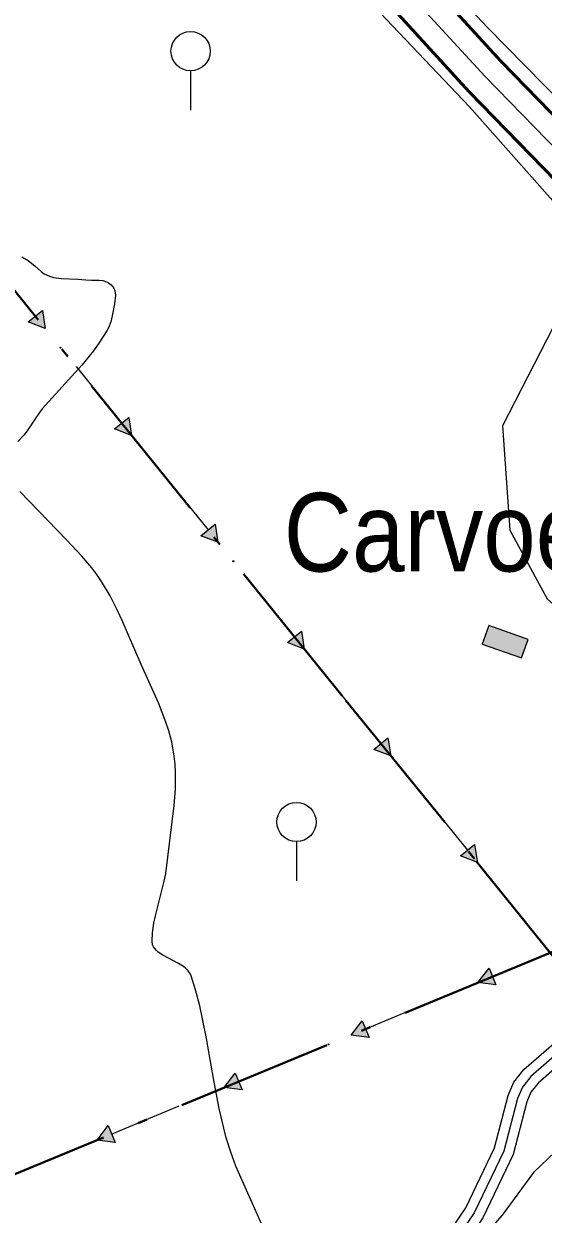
# Model space of a CAD drawing. Extents: x -64005 to -55000, y -89025 to -80000.
# Drawn here: x -59043 to -58513, y -83877 to -82664 of the extents above; entities that cross this region are included whole.
import ezdxf
from ezdxf.enums import TextEntityAlignment as Align

# ---------------------------------------------------------------- set-up
doc = ezdxf.new("R2010")
doc.units = 0
doc.header["$LTSCALE"] = 32
doc.linetypes.add('DOT_DASHED', pattern=[7.7, 5, -1.2, 0.3, -1.2])
doc.linetypes.add('LONG_DASHED', pattern=[7.5, 6, -1.5])
for name, color, linetype, lineweight in [('18', 7, 'Continuous', 25), ('2', 7, 'Continuous', 25), ('24', 7, 'Continuous', 25), ('32', 7, 'Continuous', 25), ('39', 7, 'LONG_DASHED', 25), ('7', 7, 'Continuous', 13), ('8', 7, 'Continuous', 25)]:
    doc.layers.add(name, color=color, linetype=linetype, lineweight=lineweight)
doc.layers.add('45', color=7, linetype='Continuous')

msp = doc.modelspace()

# ---------------------------------------------------------------- hatches: boundary and pattern name
at = {"layer": '18'}
for points in [[(-59023.97, -82956.59), (-59021.09, -82974.86), (-59038.36, -82968.22)], [(-58935.95, -83065.45), (-58933.07, -83083.72), (-58950.33, -83077.08)], [(-58847.92, -83174.32), (-58845.04, -83192.59), (-58862.3, -83185.95)], [(-58759.89, -83283.18), (-58757.01, -83301.45), (-58774.28, -83294.81)], [(-58671.78, -83391.94), (-58668.86, -83410.21), (-58686.14, -83403.61)], [(-58583.5, -83500.6), (-58580.58, -83518.87), (-58597.86, -83512.27)], [(-58561.62, -83643.68), (-58579.96, -83641.25), (-58568.69, -83626.58)], [(-58691.01, -83697.15), (-58709.35, -83694.72), (-58698.07, -83680.06)], [(-58820.39, -83750.63), (-58838.73, -83748.2), (-58827.46, -83733.53)], [(-58949.78, -83804.11), (-58968.11, -83801.68), (-58956.84, -83787.01)]]:
    msp.add_hatch(color=256, dxfattribs=at).paths.add_polyline_path(points)
at = {"layer": '7'}
msp.add_hatch(color=256, dxfattribs=at).paths.add_polyline_path([(-58528.85, -83291.63), (-58568.93, -83277.49), (-58575.59, -83296.35), (-58535.51, -83310.49)])

# ---------------------------------------------------------------- linework, layer by layer
at = {"layer": '18'}
for p, q in [((-59077.68, -82904.88), (-59031.16, -82962.4)), ((-58989.65, -83013.74), (-58943.14, -83071.27)), ((-58901.63, -83122.6), (-58855.11, -83180.13)), ((-58813.6, -83231.47), (-58767.09, -83289)), ((-58637.33, -83449.02), (-58590.68, -83506.44)), ((-58626.17, -83660.35), (-58694.54, -83688.61)), ((-58755.55, -83713.82), (-58823.92, -83742.08)), ((-58884.94, -83767.3), (-58953.31, -83795.56)), ((-59014.32, -83820.78), (-59082.69, -83849.03))]:
    msp.add_line(p, q, dxfattribs=at)
at = {"layer": '18', "linetype": 'DOT_DASHED', "lineweight": 40}
for points in [[(-55000.81, -81341.27), (-57492.65, -83191.85), (-58506.34, -83610.82), (-59176.97, -83888), (-59245.7, -83916.4), (-60498.5, -84434.2), (-61697.45, -84700.56), (-63379.7, -85074.29), (-63500.32, -85101.08), (-63736.4, -85153.53), (-64000, -85168.65)], [(-60219.71, -81521.05), (-59978.44, -81794.82), (-59646.58, -82111.37), (-59468.07, -82280.13), (-59415, -82487.84), (-59283.25, -82645.5), (-59128.86, -82841.58), (-58714.75, -83353.72), (-58581.73, -83517.45), (-58506.34, -83610.82), (-58347.94, -83807.01), (-58247.59, -83933.66), (-58191.9, -84001.28), (-58164.58, -84034.46), (-58137.14, -84068.11), (-57960.33, -84286.53), (-57797.76, -84487.35), (-57624.25, -84702.51), (-57366.28, -84880.22), (-57249.59, -84960.27), (-57114.47, -85053.89), (-56518.68, -85641.19), (-56404.54, -85755.57)]]:
    msp.add_lwpolyline(points, dxfattribs=at)
at = {"layer": '18'}
for points in [[(-59023.97, -82956.59), (-59021.09, -82974.86), (-59038.36, -82968.22)], [(-58935.95, -83065.45), (-58933.07, -83083.72), (-58950.33, -83077.08)], [(-58847.92, -83174.32), (-58845.04, -83192.59), (-58862.3, -83185.95)], [(-58759.89, -83283.18), (-58757.01, -83301.45), (-58774.28, -83294.81)], [(-58671.78, -83391.94), (-58668.86, -83410.21), (-58686.14, -83403.61)], [(-58583.5, -83500.6), (-58580.58, -83518.87), (-58597.86, -83512.27)], [(-58561.62, -83643.68), (-58579.96, -83641.25), (-58568.69, -83626.58)], [(-58691.01, -83697.15), (-58709.35, -83694.72), (-58698.07, -83680.06)], [(-58820.39, -83750.63), (-58838.73, -83748.2), (-58827.46, -83733.53)], [(-58949.78, -83804.11), (-58968.11, -83801.68), (-58956.84, -83787.01)]]:
    msp.add_lwpolyline(points, close=True, dxfattribs=at)
for points in [[(-58725.58, -83340.33), (-58714.75, -83353.72), (-58678.96, -83397.78)], [(-58549.17, -83557.77), (-58506.34, -83610.82), (-58502.7, -83615.33)], [(-58496.79, -83606.87), (-58506.34, -83610.82), (-58565.16, -83635.13)]]:
    msp.add_lwpolyline(points, dxfattribs=at)
for centre in [(-59005.37, -82994.3), (-58917.35, -83103.16), (-58829.32, -83212.03), (-58741.29, -83320.89), (-58653.09, -83429.61), (-58564.88, -83538.32), (-58603.06, -83650.8), (-58732.45, -83704.27), (-58861.83, -83757.75), (-58991.22, -83811.23)]:
    msp.add_circle(centre, 0.5, dxfattribs=at)
at = {"layer": '2', "lineweight": 53}
for points in [[(-58005.27, -83210), (-58013.89, -83203.14), (-58085.56, -83146.74), (-58171.15, -83072.46), (-58241.42, -83010.49), (-58351.28, -82909.11), (-58468.76, -82792.74), (-58556.36, -82702.67), (-58631.88, -82620.43), (-58703.26, -82540.92), (-58753.22, -82482.19), (-58802.18, -82423.2), (-58818.32, -82403.45)], [(-58033.51, -83245.03), (-58041.81, -83238.44), (-58114.24, -83181.44), (-58200.79, -83106.32), (-58271.56, -83043.91), (-58382.38, -82941.65), (-58500.72, -82824.42), (-58589.06, -82733.59), (-58665.2, -82650.69), (-58737.14, -82570.54), (-58787.68, -82511.13), (-58836.92, -82451.8), (-58853.29, -82431.77)]]:
    msp.add_lwpolyline(points, dxfattribs=at)
at = {"layer": '2'}
msp.add_lwpolyline([(-58019.39, -83227.52), (-58027.85, -83220.79), (-58099.9, -83164.09), (-58185.97, -83089.39), (-58256.49, -83027.2), (-58366.83, -82925.38), (-58484.74, -82808.58), (-58572.71, -82718.13), (-58648.54, -82635.56), (-58720.2, -82555.73), (-58770.45, -82496.66), (-58819.55, -82437.5), (-58835.8, -82417.61)], dxfattribs=at)
at = {"layer": '24'}
for points in [[(-59131.54, -82081.79), (-59021.28, -82238.07), (-58929.28, -82357.85), (-58846.39, -82457.48), (-58725.49, -82604.65), (-58588.62, -82749.15), (-58445.66, -82910.38), (-58503.43, -82973.52), (-58555.12, -83073.93), (-58547.5, -83180.41), (-58509.48, -83250.39), (-58386.3, -83360.66), (-58306.46, -83419.22), (-58225.88, -83296.75), (-58159.75, -83181.12), (-58131.62, -83203.18), (-58038.09, -83303.57), (-57977.77, -83366.49)], [(-57562.93, -83483.87), (-57612.28, -83458.71), (-57795.53, -83316.12), (-57916.42, -83244.63), (-58069.26, -83129.04), (-58158.22, -83044.62), (-58191.68, -83037.78), (-58357.46, -82884.53), (-58570.37, -82668.16), (-58698.88, -82531.26), (-58808.38, -82396.65), (-58888.98, -82290.17), (-58953.16, -82217.01)], [(-58800.72, -83887.2), (-58826.72, -83828.35), (-58831.99, -83813.99), (-58836.5, -83799.34), (-58839.15, -83789.44), (-58843.78, -83769.37), (-58849.55, -83738.87), (-58856.65, -83698.14), (-58860.61, -83678.04), (-58863.6, -83664.83), (-58867.89, -83648.59), (-58872.4, -83634.3), (-58873.14, -83632.54), (-58875.25, -83629.36), (-58878.06, -83626.53), (-58880.26, -83624.82), (-58885.21, -83621.71), (-58901.3, -83613.28), (-58905.86, -83610.2), (-58907.8, -83608.52), (-58910.73, -83604.75), (-58911.64, -83602.62), (-58912.19, -83599.06), (-58911.77, -83590.44), (-58910.4, -83580.81), (-58908.8, -83573.08), (-58899.75, -83537.99), (-58898.13, -83530.13), (-58889.48, -83460.97), (-58888.25, -83444.03), (-58888.11, -83427.17), (-58888.58, -83418.78), (-58889.48, -83410.42), (-58892.15, -83395.96), (-58895.14, -83384.7), (-58898, -83375.8), (-58905.61, -83356.08), (-58923.26, -83317.12), (-58942.59, -83272.48), (-58947.33, -83262.17), (-58954.99, -83247.06), (-58963.62, -83232.55), (-58968.42, -83225.58), (-58973.58, -83218.83), (-58983.89, -83206.87), (-58999.37, -83190), (-59047.05, -83140.92)], [(-58423.67, -83812.69), (-58447.31, -83806.67), (-58470.12, -83805.91), (-58501.29, -83813.52), (-58523.34, -83834.83), (-58555.27, -83878.19), (-58582.63, -83909), (-58629.77, -83962.25), (-58674.78, -84023.88)]]:
    msp.add_lwpolyline(points, dxfattribs=at)
at = {"layer": '32'}
for p, q in [((-58872.87, -82712.35), (-58872.87, -82752.35)), ((-58764.98, -83497.66), (-58764.98, -83537.66))]:
    msp.add_line(p, q, dxfattribs=at)
for centre in [(-58872.87, -82692.35), (-58764.98, -83477.66)]:
    msp.add_circle(centre, 20, dxfattribs=at)
at = {"layer": '39'}
msp.add_lwpolyline([(-58360.97, -83600.52), (-58414.02, -83637.24), (-58428.6, -83648.81), (-58480.78, -83697.38), (-58526.08, -83736.8), (-58534.63, -83747.86), (-58539.65, -83759.43), (-58553.66, -83813.01), (-58583.81, -83875.86), (-58627.03, -83939.3), (-58636.07, -83954.8), (-58676.14, -84024.52), (-58682.72, -84046.47), (-58685.23, -84066.58), (-58686.74, -84087.2), (-58681.21, -84129.43), (-58665.83, -84178.22), (-58657.1, -84191.64), (-58643.54, -84203.21), (-58624.04, -84214.06), (-58543.46, -84255.87)], dxfattribs=at)
at = {"layer": '7', "lineweight": 25}
msp.add_lwpolyline([(-59045.02, -82901.72), (-59038.49, -82905.61), (-59031.38, -82911.22), (-59025.25, -82916.63), (-59021.98, -82919.01), (-59016.57, -82921.69), (-59012.56, -82922.83), (-59004.4, -82924.05), (-58987.8, -82924.63), (-58979.54, -82925.3), (-58973.78, -82925.58), (-58966.13, -82925.59), (-58962.34, -82926.11), (-58958.57, -82927.37), (-58956.7, -82928.37), (-58953.92, -82930.43), (-58952.13, -82932.33), (-58951.24, -82933.67), (-58950.07, -82936.48), (-58949.53, -82940.91), (-58950.58, -82949.77), (-58952.67, -82962.08), (-58954.31, -82968.21), (-58956.7, -82974.22), (-58958.27, -82977.16), (-58966.28, -82989.75), (-58971.88, -82997.48), (-58983.89, -83012.25), (-59024.04, -83056.76), (-59026.93, -83060.33), (-59032.12, -83067.9), (-59038.78, -83078.25), (-59042.42, -83083.24), (-59048.82, -83090.15)], dxfattribs=at)
at = {"layer": '7'}
msp.add_lwpolyline([(-58528.85, -83291.63), (-58568.93, -83277.49), (-58575.59, -83296.35), (-58535.51, -83310.49)], close=True, dxfattribs=at)
at = {"layer": '8', "linetype": 'LONG_DASHED'}
msp.add_lwpolyline([(-58674.95, -84182.55), (-58691.01, -84131.6), (-58696.79, -84087.49), (-58695.18, -84065.59), (-58692.53, -84044.37), (-58691.33, -84040.45), (-58686.25, -84025.39), (-58682.04, -84015.99), (-58644.75, -83949.83), (-58635.49, -83933.96), (-58592.5, -83870.85), (-58563.09, -83809.55), (-58549.13, -83756.16), (-58543.31, -83742.73), (-58533.39, -83729.9), (-58487.47, -83689.95), (-58435.12, -83641.22), (-58419.98, -83629.2), (-58383.89, -83604.22)], dxfattribs=at)
at = {"layer": '8'}
msp.add_lwpolyline([(-58354.66, -83608.31), (-58408.06, -83645.28), (-58422.08, -83656.4), (-58474.09, -83704.81), (-58518.77, -83743.7), (-58525.95, -83752.99), (-58530.17, -83762.7), (-58544.23, -83816.47), (-58575.12, -83880.87), (-58618.57, -83944.64), (-58627.39, -83959.77), (-58667.45, -84030.83), (-58672.91, -84048.57), (-58675.28, -84067.57), (-58676.69, -84086.91), (-58671.41, -84127.26), (-58654.58, -84180.64)], dxfattribs=at)

# ---------------------------------------------------------------- texts
at = {"layer": '45', "width": 0.9}
msp.add_text('Carvoeira', height=80, rotation=0.007, dxfattribs=at).set_placement((-58569.22, -83222.38), align=Align.CENTER)

doc.saveas('drawing.dxf')
